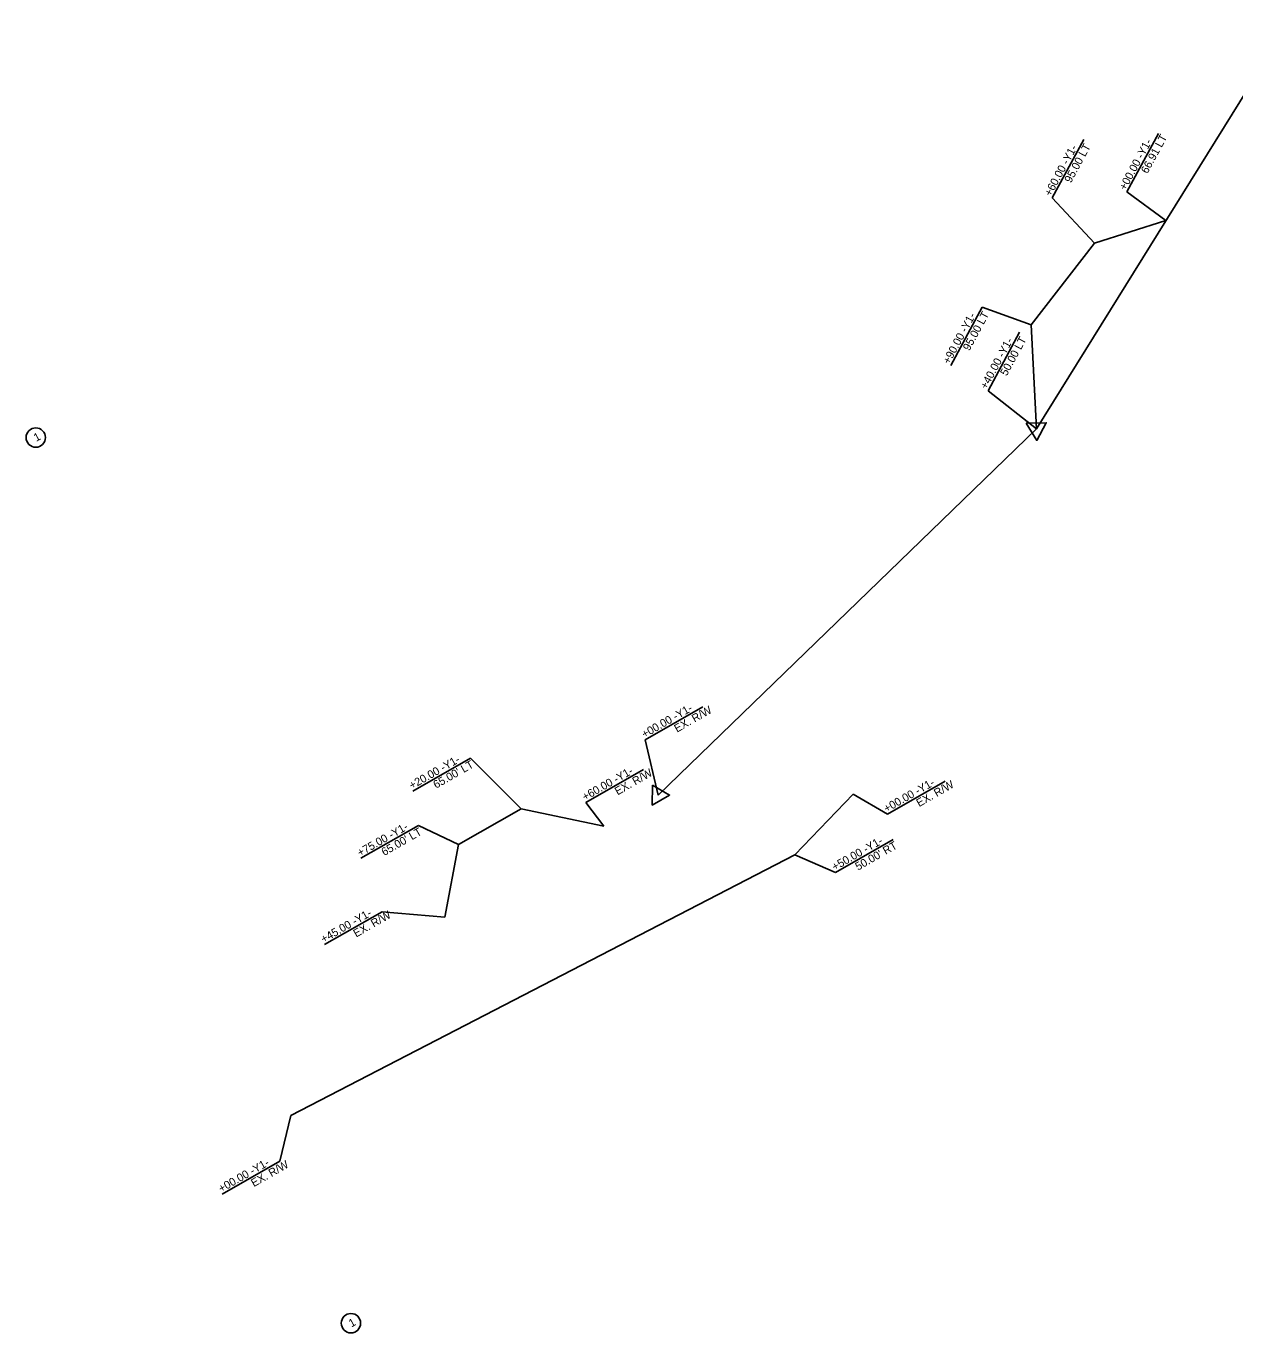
# Model space of a CAD drawing. Extents: x 2345854 to 2349056, y 842589 to 845145.
# Drawn here: x 2345854 to 2346609, y 842589 to 843405 of the extents above; entities that cross this region are included whole.
import ezdxf

# ---------------------------------------------------------------- set-up
doc = ezdxf.new("R2010")
doc.units = 0
for name, color, linetype in [('Prop Easement Construction', 7, 'Continuous'), ('Prop Easement Construction Station Offsets', 7, 'Continuous'), ('Prop Parcel Number Text', 7, 'Continuous'), ('Prop ROW Marker CELL', 7, 'Continuous'), ('Prop ROW RW Lines', 7, 'Continuous'), ('Prop ROW Station Offsets', 7, 'Continuous')]:
    doc.layers.add(name, color=color, linetype=linetype)

msp = doc.modelspace()

# ---------------------------------------------------------------- linework, layer by layer
at = {"layer": 'Prop Easement Construction'}
for p, q in [((2346521.17, 843269.94), (2346565.74, 843284.14)), ((2346481.39, 843218.95), (2346521.17, 843269.94)), ((2346484.79, 843153.91), (2346481.39, 843218.95)), ((2346123.74, 842894.16), (2346162.8, 842916.49)), ((2346162.8, 842916.49), (2346214.46, 842905.7)), ((2346115.06, 842848.89), (2346123.74, 842894.16))]:
    msp.add_line(p, q, dxfattribs=at)
msp.add_lwpolyline([(2346018.95, 842724.84), (2346333.91, 842887.77), (2346370.38, 842925.72)], dxfattribs=at)
at = {"layer": 'Prop Easement Construction Station Offsets'}
for p, q in [((2346131.11, 842948.21), (2346095.1, 842927.62)), ((2346239.25, 842941.06), (2346203.24, 842920.47)), ((2346427.67, 842933.74), (2346391.67, 842913.15)), ((2346098.73, 842906.18), (2346062.72, 842885.59)), ((2346395.29, 842897.35), (2346359.28, 842876.76)), ((2346075.91, 842852.25), (2346039.9, 842831.65)), ((2346011.97, 842696.32), (2345975.96, 842675.73))]:
    msp.add_line(p, q, dxfattribs=at)
for points in [[(2346131.11, 842948.21), (2346162.8, 842916.49)], [(2346391.67, 842913.15), (2346370.38, 842925.72)], [(2346203.24, 842920.47), (2346214.46, 842905.7)], [(2346098.73, 842906.18), (2346123.74, 842894.16)], [(2346359.28, 842876.76), (2346333.91, 842887.77)], [(2346075.91, 842852.25), (2346115.06, 842848.89)], [(2346011.97, 842696.32), (2346018.95, 842724.84)]]:
    msp.add_lwpolyline(points, dxfattribs=at)
at = {"layer": 'Prop Parcel Number Text'}
for centre in [(2345859.58, 843148.47), (2346056.47, 842595.18)]:
    msp.add_circle(centre, 6.05, dxfattribs=at)
at = {"layer": 'Prop ROW Marker CELL'}
for p, q in [((2346484.79, 843153.91), (2346484.79, 843153.91)), ((2346248.39, 842925.1), (2346248.39, 842925.1))]:
    msp.add_line(p, q, dxfattribs=at)
for points in [[(2346478.45, 843157.35), (2346490.92, 843157.67), (2346484.99, 843146.7)], [(2346244.82, 842931.36), (2346255.59, 842925.06), (2346244.76, 842918.86)]]:
    msp.add_lwpolyline(points, close=True, dxfattribs=at)
at = {"layer": 'Prop ROW RW Lines'}
for p, q in [((2346484.79, 843153.91), (2346641.17, 843405.47)), ((2346248.39, 842925.1), (2346484.79, 843153.91))]:
    msp.add_line(p, q, dxfattribs=at)
at = {"layer": 'Prop ROW Station Offsets'}
for p, q in [((2346514.39, 843334.75), (2346494.67, 843298.26)), ((2346561.09, 843338.47), (2346541.37, 843301.98)), ((2346450.94, 843229.9), (2346431.22, 843193.41)), ((2346474.27, 843214.22), (2346454.55, 843177.73)), ((2346276.38, 842980.25), (2346240.37, 842959.66))]:
    msp.add_line(p, q, dxfattribs=at)
for points in [[(2346541.37, 843301.98), (2346565.74, 843284.14)], [(2346494.67, 843298.26), (2346521.17, 843269.94)], [(2346450.94, 843229.9), (2346481.39, 843218.95)], [(2346454.55, 843177.73), (2346484.79, 843153.91)], [(2346240.37, 842959.66), (2346248.39, 842925.1)]]:
    msp.add_lwpolyline(points, dxfattribs=at)

# ---------------------------------------------------------------- texts
at = {"layer": 'Prop Easement Construction Station Offsets'}
for s, p in [('+20.00 -Y1-', (2346094.58, 842928.53)), ("65.00' LT", (2346109.66, 842928.99)), ('+60.00 -Y1-', (2346202.73, 842921.37)), ('EX. R/W', (2346223.08, 842924.85)), ('+00.00 -Y1-', (2346391.15, 842914.06)), ('EX. R/W', (2346411.5, 842917.54)), ('+75.00 -Y1-', (2346062.2, 842886.5)), ("65.00' LT", (2346077.28, 842886.96)), ('+50.00 -Y1-', (2346358.76, 842877.66)), ("50.00' RT", (2346373.33, 842877.83)), ('+45.00 -Y1-', (2346039.39, 842832.56)), ('EX. R/W', (2346059.74, 842836.04)), ('+00.00 -Y1-', (2345975.45, 842676.64)), ('EX. R/W', (2345995.8, 842680.12))]:
    msp.add_text(s, height=5, rotation=29.76453, dxfattribs=at).set_placement(p)
at = {"layer": 'Prop Parcel Number Text'}
for p in [(2345859.83, 843145.76), (2346056.72, 842592.47)]:
    msp.add_text('1', height=5, rotation=28.33559, dxfattribs=at).set_placement(p)
at = {"layer": 'Prop ROW Station Offsets'}
for s, rotation, p in [('+00.00 -Y1-', 61.61241, (2346540.45, 843302.47)), ('66.91 LT', 61.61241, (2346554.15, 843312.93)), ('+60.00 -Y1-', 61.61241, (2346493.76, 843298.75)), ('95.00 LT', 61.61241, (2346506.32, 843307.1)), ('95.00 LT', 61.61241, (2346442.87, 843202.26)), ('+90.00 -Y1-', 61.61241, (2346430.31, 843193.91)), ('50.00 LT', 61.61241, (2346466.2, 843186.57)), ('+40.00 -Y1-', 61.61241, (2346453.63, 843178.22)), ('+00.00 -Y1-', 29.76453, (2346239.86, 842960.57)), ('EX. R/W', 29.76453, (2346260.21, 842964.05))]:
    msp.add_text(s, height=5, rotation=rotation, dxfattribs=at).set_placement(p)

doc.saveas('drawing.dxf')
